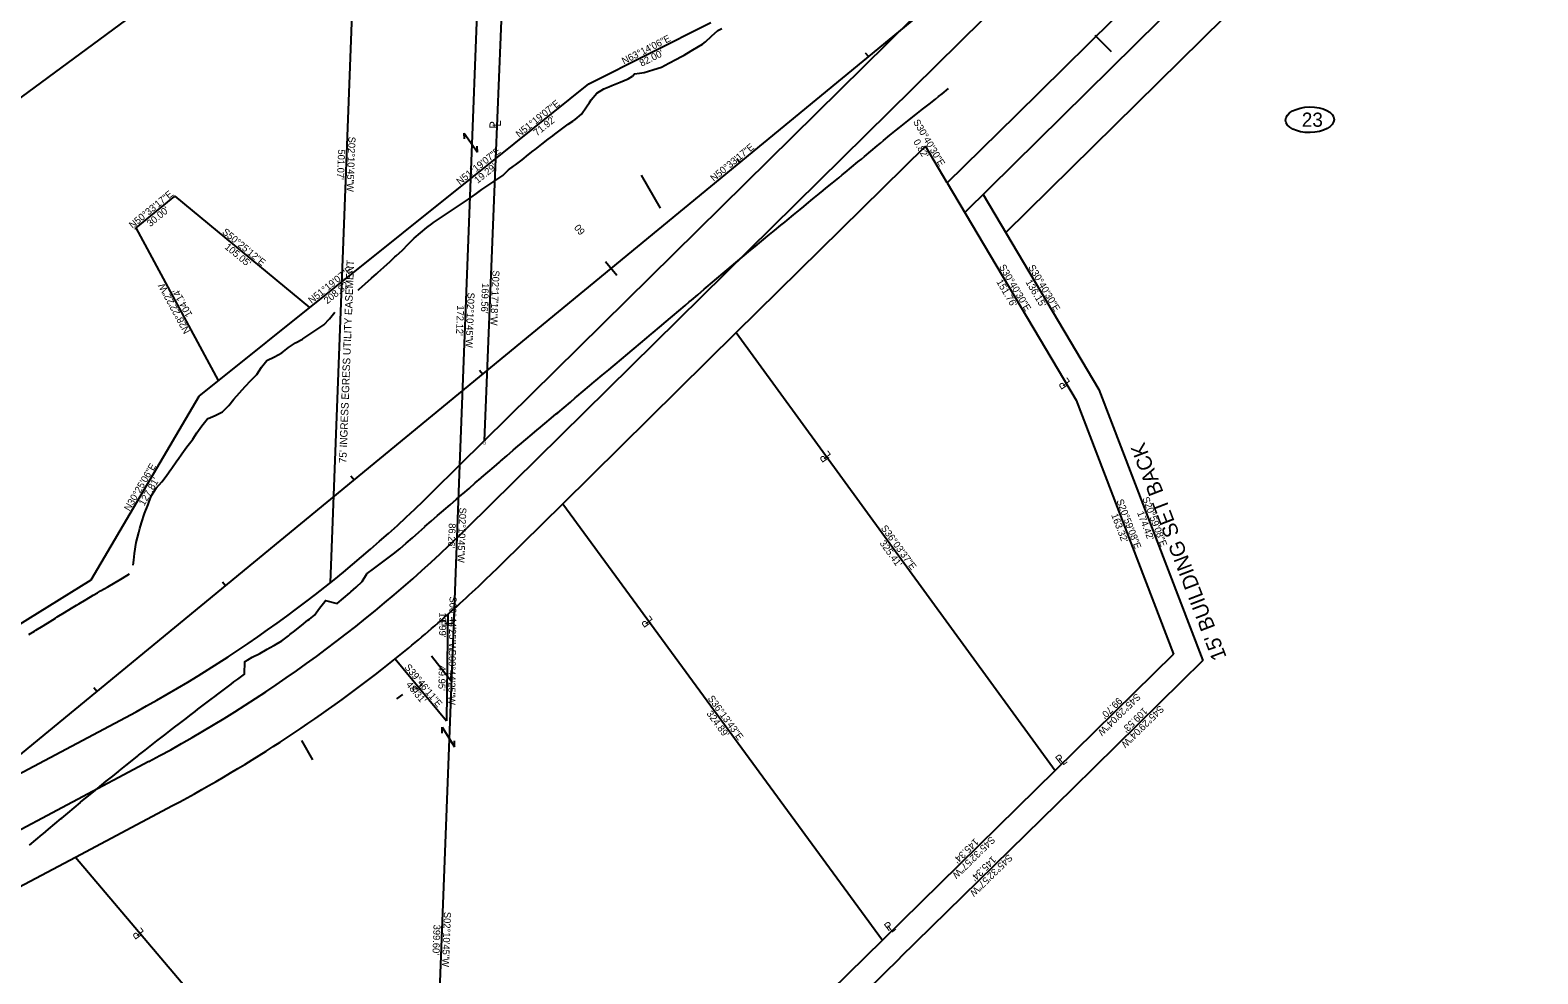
# Model space of a CAD drawing. Extents: x 1145508 to 2262867, y -3126236 to 2021677.
# Drawn here: x 1148734 to 1149640, y 2018227 to 2018793 of the extents above; entities that cross this region are included whole.
import ezdxf

# ---------------------------------------------------------------- set-up
doc = ezdxf.new("R2010")
doc.units = 0
for name, color, linetype in [('Default', 7, 'Continuous'), ('DSN_RDWY_Alignment Annotation', 7, 'Continuous'), ('DSN_RDWY_Const Limits', 7, 'Continuous'), ('DSN_ROW_Annotation', 7, 'Continuous'), ('DSN_ROW_Esmnt', 7, 'Continuous'), ('DSN_ROW_Line', 7, 'Continuous'), ('DSN_ROW_Line-Annotation', 7, 'Continuous'), ('DSN_ROW_Prop-Line', 7, 'Continuous'), ('DSN_ROW_Prop-Line-Annotation', 7, 'Continuous'), ('E_Const Align', 7, 'Continuous'), ('EX_PRIMARY_CTL', 7, 'Continuous'), ('EX_QSECTION', 7, 'Continuous'), ('EX_ROW', 7, 'Continuous'), ('EX_ROW_ANNOT', 7, 'Continuous'), ('EX_SIGN', 7, 'Continuous')]:
    doc.layers.add(name, color=color, linetype=linetype)

msp = doc.modelspace()

# ---------------------------------------------------------------- linework, layer by layer
at = {"layer": 'Default'}
for p, q in [((1149548.89, 2019038.9), (1148996.69, 2018494.41)), ((1148805.68, 2018354.22), (1148567.35, 2018227.75))]:
    msp.add_line(p, q, dxfattribs=at)
msp.add_arc((1148422, 2019077.24), 818.51, 297.95351, 314.5973, dxfattribs=at)
at = {"layer": 'DSN_RDWY_Alignment Annotation'}
for p, q in [((1149235.9, 2018779.81), (1149237.81, 2018777.49)), ((1149158.68, 2018716.28), (1149160.58, 2018713.96)), ((1149079.97, 2018654.55), (1149086.71, 2018646.35)), ((1149004.23, 2018589.21), (1149006.14, 2018586.89)), ((1148927.01, 2018525.67), (1148928.91, 2018523.36)), ((1148849.78, 2018462.14), (1148851.69, 2018459.82)), ((1148772.56, 2018398.61), (1148774.47, 2018396.29))]:
    msp.add_line(p, q, dxfattribs=at)
at = {"layer": 'DSN_RDWY_Const Limits'}
for points in [[(1148931.32, 2018637.33), (1148931.86, 2018637.82), (1148935.61, 2018641.14), (1148939.35, 2018644.45), (1148942.37, 2018647.15), (1148943.1, 2018647.77), (1148946.8, 2018651.14), (1148950.51, 2018654.5), (1148953.45, 2018657.17), (1148954.21, 2018657.87), (1148957.92, 2018661.24), (1148961.41, 2018664.86), (1148964.09, 2018667.7), (1148964.87, 2018668.53), (1148968.69, 2018671.76), (1148972.62, 2018674.85), (1148975.6, 2018677.18), (1148976.55, 2018677.93), (1148980.71, 2018680.75), (1148984.92, 2018683.51), (1148988.01, 2018685.56), (1148989.12, 2018686.28), (1148993.34, 2018689.01), (1148997.52, 2018691.81), (1149000.46, 2018693.91), (1149001.59, 2018694.72), (1149005.67, 2018697.63), (1149009.83, 2018700.44), (1149012.73, 2018702.47), (1149013.97, 2018703.28), (1149018.16, 2018706.06), (1149021.72, 2018709.61), (1149024.63, 2018711.69), (1149025.79, 2018712.52), (1149029.74, 2018715.6), (1149033.66, 2018718.7), (1149036.35, 2018720.83), (1149037.58, 2018721.81), (1149041.55, 2018724.85), (1149045.53, 2018727.88), (1149048.2, 2018729.92), (1149049.51, 2018730.92), (1149053.48, 2018733.96), (1149057.5, 2018736.94), (1149060.22, 2018738.81), (1149061.64, 2018739.78), (1149065.5, 2018742.96), (1149068.43, 2018747.27), (1149070.31, 2018750.03), (1149071.36, 2018751.57), (1149074.59, 2018755.52), (1149078.9, 2018758.15), (1149081.94, 2018759.38), (1149083.76, 2018760.12), (1149088.61, 2018762.09), (1149093.42, 2018764.12), (1149096.05, 2018765.8), (1149097.4, 2018767.14), (1149100.37, 2018767.53), (1149103.15, 2018768.02), (1149108.31, 2018769.62), (1149111.5, 2018770.49), (1149113.51, 2018771.17), (1149117.95, 2018773.65), (1149122.54, 2018775.94), (1149125.2, 2018777.27), (1149127.04, 2018778.34), (1149131.41, 2018780.89), (1149135.75, 2018783.5), (1149138.16, 2018785.01), (1149139.9, 2018786.31), (1149143.55, 2018789.75), (1149147.27, 2018793.1), (1149149.7, 2018794.43)], [(1148733.93, 2018303.9), (1148737.73, 2018307.16), (1148741.56, 2018310.37), (1148742.1, 2018310.83), (1148745.39, 2018313.58), (1148749.23, 2018316.79), (1148753.04, 2018320.02), (1148753.35, 2018320.29), (1148756.85, 2018323.27), (1148760.71, 2018326.45), (1148764.53, 2018329.66), (1148764.6, 2018329.72), (1148766.77, 2018331.54), (1148768.39, 2018332.85), (1148772.27, 2018336.01), (1148775.95, 2018339.01), (1148776.14, 2018339.17), (1148780.02, 2018342.32), (1148783.91, 2018345.46), (1148787.37, 2018348.24), (1148787.81, 2018348.59), (1148791.69, 2018351.74), (1148795.58, 2018354.89), (1148798.73, 2018357.44), (1148799.47, 2018358.03), (1148803.4, 2018361.12), (1148807.33, 2018364.21), (1148810.34, 2018366.55), (1148811.29, 2018367.27), (1148815.26, 2018370.32), (1148819.23, 2018373.36), (1148821.87, 2018375.4), (1148823.18, 2018376.42), (1148827.15, 2018379.47), (1148831.11, 2018382.52), (1148833.39, 2018384.28), (1148835.08, 2018385.58), (1148839.03, 2018388.64), (1148843.01, 2018391.67), (1148845.18, 2018393.26), (1148847.06, 2018394.63), (1148851.1, 2018397.58), (1148855.01, 2018400.7), (1148856.68, 2018402.05), (1148858.98, 2018403.74), (1148863.02, 2018406.71), (1148863.22, 2018414.33), (1148865.02, 2018415.35), (1148867.65, 2018416.82), (1148872.19, 2018419.16), (1148876.65, 2018421.61), (1148878.16, 2018422.46), (1148881.07, 2018424.12), (1148885.43, 2018426.69), (1148889.4, 2018429.73), (1148890.38, 2018430.48), (1148893.36, 2018432.78), (1148896.47, 2018435.3), (1148897.25, 2018435.93), (1148901.19, 2018439), (1148902.15, 2018439.73), (1148905.09, 2018442.14), (1148908.17, 2018446.27), (1148911.24, 2018450.4), (1148911.67, 2018450.99), (1148918.75, 2018449.14), (1148922.6, 2018452.34), (1148926.4, 2018455.59), (1148926.92, 2018456.04), (1148930.12, 2018458.93), (1148933.8, 2018462.33), (1148936.55, 2018466.86), (1148936.77, 2018467.03), (1148940.55, 2018469.87), (1148944.54, 2018472.88), (1148948.54, 2018475.89), (1148948.54, 2018475.89), (1148952.54, 2018478.9), (1148956.45, 2018482.02), (1148960.2, 2018485.27), (1148960.23, 2018485.29), (1148963.97, 2018488.61), (1148967.72, 2018491.93), (1148971.34, 2018495.14), (1148971.46, 2018495.25), (1148975.21, 2018498.56), (1148978.96, 2018501.88), (1148982.56, 2018505.04), (1148982.72, 2018505.18), (1148986.51, 2018508.44), (1148990.32, 2018511.68), (1148993.68, 2018514.54), (1148994.13, 2018514.92), (1148997.9, 2018518.2), (1149001.67, 2018521.49), (1149004.97, 2018524.31), (1149005.47, 2018524.74), (1149009.27, 2018527.99), (1149013.06, 2018531.25), (1149016.29, 2018534.05), (1149016.84, 2018534.53), (1149020.61, 2018537.82), (1149024.39, 2018541.1), (1149027.45, 2018543.75), (1149028.16, 2018544.38), (1149031.94, 2018547.66), (1149035.78, 2018550.86), (1149038.82, 2018553.4), (1149039.62, 2018554.06), (1149043.46, 2018557.26), (1149047.32, 2018560.45), (1149050.3, 2018562.92), (1149051.16, 2018563.64), (1149054.99, 2018566.86), (1149058.81, 2018570.08), (1149061.71, 2018572.52), (1149062.64, 2018573.31), (1149066.46, 2018576.53), (1149070.28, 2018579.76), (1149073.1, 2018582.14), (1149074.1, 2018582.98), (1149077.94, 2018586.18), (1149081.79, 2018589.38), (1149084.56, 2018591.69), (1149085.62, 2018592.58), (1149089.45, 2018595.8), (1149093.28, 2018599.01), (1149095.99, 2018601.27), (1149097.12, 2018602.22), (1149100.94, 2018605.45), (1149104.75, 2018608.68), (1149107.48, 2018610.99), (1149108.57, 2018611.91), (1149112.4, 2018615.13), (1149116.23, 2018618.35), (1149118.86, 2018620.55), (1149120.06, 2018621.56), (1149123.87, 2018624.79), (1149127.68, 2018628.04), (1149130.23, 2018630.22), (1149131.48, 2018631.28), (1149135.28, 2018634.53), (1149139.09, 2018637.78), (1149141.59, 2018639.91), (1149142.89, 2018641.02), (1149146.7, 2018644.26), (1149150.53, 2018647.48), (1149152.99, 2018649.54), (1149154.36, 2018650.7), (1149158.19, 2018653.91), (1149162.02, 2018657.12), (1149164.42, 2018659.13), (1149165.87, 2018660.32), (1149169.74, 2018663.48), (1149173.61, 2018666.65), (1149176.01, 2018668.61), (1149177.48, 2018669.82), (1149179.43, 2018671.44), (1149181.32, 2018673.01), (1149185.18, 2018676.19), (1149187.51, 2018678.11), (1149189.04, 2018679.37), (1149192.89, 2018682.56), (1149196.75, 2018685.73), (1149199, 2018687.58), (1149200.62, 2018688.91), (1149204.48, 2018692.08), (1149208.36, 2018695.24), (1149210.54, 2018697.03), (1149212.23, 2018698.41), (1149216.09, 2018701.58), (1149219.97, 2018704.73), (1149222.08, 2018706.45), (1149223.84, 2018707.9), (1149227.68, 2018711.1), (1149231.52, 2018714.3), (1149233.56, 2018715.99), (1149235.38, 2018717.49), (1149239.19, 2018720.72), (1149243.01, 2018723.94), (1149244.98, 2018725.59), (1149246.85, 2018727.15), (1149250.73, 2018730.3), (1149254.61, 2018733.46), (1149256.54, 2018735.03), (1149258.49, 2018736.61), (1149262.41, 2018739.72), (1149266.33, 2018742.82), (1149268.23, 2018744.31), (1149270.27, 2018745.91), (1149274.21, 2018748.98), (1149278.17, 2018752.04), (1149279.97, 2018753.49), (1149282.05, 2018755.2), (1149285.85, 2018758.44)], [(1148796.25, 2018472.11), (1148796.55, 2018475.14), (1148796.95, 2018479.14), (1148798.02, 2018485.71), (1148799.6, 2018491.65), (1148800.25, 2018494.08), (1148801.19, 2018497.59), (1148803.09, 2018503.16), (1148805.12, 2018508.56), (1148805.81, 2018510.4), (1148807.15, 2018513.96), (1148810.08, 2018518.26), (1148813.39, 2018522.11), (1148814.21, 2018523.07), (1148816.48, 2018526.23), (1148818.87, 2018529.62), (1148819.47, 2018530.46), (1148822.45, 2018534.71), (1148823.17, 2018535.72), (1148825.44, 2018538.95), (1148828.43, 2018543.18), (1148831.6, 2018547.2), (1148832, 2018547.82), (1148834.43, 2018551.63), (1148837.44, 2018555.84), (1148840.6, 2018559.87), (1148841.23, 2018560.19), (1148845.38, 2018561.93), (1148849.92, 2018564.28), (1148853.48, 2018567.83), (1148853.67, 2018568.02), (1148856.7, 2018571.78), (1148860.06, 2018575.57), (1148863.37, 2018579.41), (1148863.37, 2018579.41), (1148866.85, 2018583.05), (1148870.4, 2018586.6), (1148873.23, 2018590.99), (1148873.24, 2018591.02), (1148876.49, 2018594.95), (1148881.04, 2018597.29), (1148885.41, 2018599.59), (1148885.55, 2018599.67), (1148889.45, 2018602.8), (1148893.62, 2018605.6), (1148897.97, 2018607.87), (1148898.16, 2018607.96), (1148902.33, 2018610.75), (1148906.5, 2018613.56), (1148910.14, 2018616.08), (1148910.61, 2018616.44), (1148914.07, 2018620.1), (1148917.33, 2018624)], [(1148733.44, 2018430.41), (1148736.93, 2018432.55), (1148737.74, 2018433.05), (1148742.04, 2018435.7), (1148746.34, 2018438.35), (1148749.61, 2018440.36), (1148750.61, 2018441.02), (1148754.9, 2018443.68), (1148759.2, 2018446.32), (1148762.06, 2018448.09), (1148763.5, 2018448.97), (1148767.87, 2018451.53), (1148772.22, 2018454.1), (1148774.73, 2018455.58), (1148776.58, 2018456.67), (1148780.99, 2018459.19), (1148785.35, 2018461.76), (1148787.68, 2018463.15), (1148789.7, 2018464.34), (1148794.05, 2018466.92)]]:
    msp.add_lwpolyline(points, dxfattribs=at)
at = {"layer": 'DSN_ROW_Esmnt'}
for p, q in [((1148797.98, 2018674.63), (1148821.15, 2018693.69)), ((1148797.98, 2018674.63), (1148821.15, 2018693.69)), ((1148821.15, 2018693.69), (1148902.12, 2018626.75)), ((1148821.15, 2018693.69), (1148902.12, 2018626.75)), ((1148847.47, 2018583), (1148797.98, 2018674.63)), ((1148847.47, 2018583), (1148797.98, 2018674.63))]:
    msp.add_line(p, q, dxfattribs=at)
at = {"layer": 'DSN_ROW_Line'}
for p, q in [((1149069.97, 2018761.14), (1149143.19, 2018798.06)), ((1149013.83, 2018716.19), (1149069.97, 2018761.14)), ((1148998.77, 2018704.13), (1149013.83, 2018716.19)), ((1148835.76, 2018573.62), (1148998.77, 2018704.13)), ((1148771.05, 2018463.4), (1148835.76, 2018573.62)), ((1148642.51, 2018383.55), (1148771.05, 2018463.4))]:
    msp.add_line(p, q, dxfattribs=at)
at = {"layer": 'DSN_ROW_Line-Annotation'}
msp.add_ellipse((1149502.94, 2018739.58), major_axis=(14.54, 0.23), ratio=0.529773, dxfattribs=at)
at = {"layer": 'DSN_ROW_Prop-Line'}
for p, q in [((1148375.95, 2018492.82), (1149008.48, 2018959.29)), ((1148933.53, 2018962.14), (1148914.48, 2018461.44)), ((1149023.52, 2018958.62), (1149013.83, 2018716.19)), ((1149295.7, 2018683.91), (1149563.53, 2018948)), ((1149320.31, 2018671.82), (1149594.73, 2018942.42)), ((1149272.05, 2018723.79), (1149272.46, 2018723.08)), ((1149013.83, 2018716.19), (1149007.06, 2018546.76)), ((1149285.19, 2018701.63), (1149362.61, 2018571.11)), ((1149306.7, 2018694.76), (1149376.16, 2018577.67)), ((1149158.46, 2018611.78), (1149350, 2018348.72)), ((1149376.16, 2018577.67), (1149438.62, 2018414.82)), ((1149362.61, 2018571.11), (1149421.1, 2018418.62)), ((1149054.24, 2018509.02), (1149246.25, 2018246.94)), ((1148985.2, 2018442.59), (1148985.02, 2018428.6)), ((1148985.02, 2018428.6), (1148984.37, 2018378.65)), ((1148953.46, 2018415.79), (1148984.37, 2018378.65)), ((1149421.1, 2018418.62), (1149350, 2018348.72)), ((1149438.62, 2018414.82), (1149360.52, 2018338.03)), ((1149350, 2018348.72), (1149246.25, 2018246.94)), ((1149360.51, 2018338.02), (1149256.76, 2018236.23)), ((1148761.6, 2018296.87), (1149062.47, 2017941.97)), ((1149246.25, 2018246.94), (1149174.9, 2018177.17)), ((1149256.74, 2018236.22), (1149194.74, 2018175.59))]:
    msp.add_line(p, q, dxfattribs=at)
at = {"layer": 'DSN_ROW_Prop-Line-Annotation'}
for p, q in [((1148995.13, 2018728.05), (1148994.92, 2018731.59)), ((1148994.92, 2018731.59), (1149002.98, 2018720.18)), ((1149002.98, 2018720.18), (1149002.78, 2018723.72)), ((1148981.86, 2018371.31), (1148981.86, 2018374.86)), ((1148981.86, 2018374.86), (1148989.25, 2018363)), ((1148989.25, 2018363), (1148989.25, 2018366.55))]:
    msp.add_line(p, q, dxfattribs=at)
at = {"layer": 'E_Const Align'}
msp.add_line((1148677.53, 2018316.54), (1149639.88, 2019108.3), dxfattribs=at)
at = {"layer": 'EX_QSECTION'}
for p, q in [((1149008.48, 2018959.29), (1148998.77, 2018704.13)), ((1148998.77, 2018704.13), (1148992.23, 2018532.14)), ((1148992.23, 2018532.14), (1148988.95, 2018445.93)), ((1148988.95, 2018445.93), (1148973.75, 2018046.62))]:
    msp.add_line(p, q, dxfattribs=at)
at = {"layer": 'EX_ROW'}
for p, q in [((1149326.65, 2018742.52), (1149523.2, 2018936.33)), ((1149007.06, 2018546.76), (1149326.33, 2018861.58)), ((1149285.19, 2018701.63), (1149326.65, 2018742.52)), ((1149158.46, 2018611.78), (1149272.05, 2018723.79)), ((1149285.19, 2018701.63), (1149272.05, 2018723.79)), ((1149054.24, 2018509.02), (1149158.46, 2018611.78)), ((1148992.23, 2018532.14), (1149007.06, 2018546.76)), ((1148975.63, 2018515.77), (1148992.23, 2018532.14)), ((1149017.76, 2018473.05), (1149054.24, 2018509.02)), ((1148553.28, 2018254.25), (1148791.62, 2018380.72)), ((1148761.6, 2018296.87), (1148819.75, 2018327.73)), ((1148705.7, 2018267.2), (1148761.6, 2018296.87))]:
    msp.add_line(p, q, dxfattribs=at)
for radius, start, end in [(788.51, 297.95351, 314.5973), (848.51, 311.92551, 314.5973), (848.51, 308.78113, 311.58612), (848.51, 311.58612, 311.92551), (848.51, 297.95351, 308.78113)]:
    msp.add_arc((1148422, 2019077.24), radius, start, end, dxfattribs=at)
at = {"layer": 'EX_SIGN'}
for p, q in [((1149373.79, 2018790.45), (1149383.63, 2018780.52)), ((1149101.25, 2018706.24), (1149112.72, 2018686.56)), ((1148975.36, 2018417.76), (1148987.78, 2018401.78)), ((1148958.05, 2018394.47), (1148954.35, 2018391.79)), ((1148897.31, 2018366.83), (1148903.98, 2018355.25))]:
    msp.add_line(p, q, dxfattribs=at)

# ---------------------------------------------------------------- texts
at = {"layer": 'DSN_RDWY_Alignment Annotation'}
for s, rotation, p in [('N50°33\'17"E', 39.44534, (1149144.96, 2018702.27)), ('60', 129.44534, (1149067.94, 2018672.48))]:
    msp.add_text(s, height=4.2, rotation=rotation, dxfattribs=at).set_placement(p)
at = {"layer": 'DSN_ROW_Annotation'}
for s, rotation, p in [('N63°14\'06"E', 26.76495, (1149090.94, 2018772.72)), ("82.00'", 26.76495, (1149101.6, 2018771.38)), ('N51°19\'07"E', 38.68144, (1149028.02, 2018728.7)), ("71.92'", 38.68144, (1149038.72, 2018729.59)), ('S30°40\'30"E', 300.67507, (1149264.48, 2018738.31)), ('S02°10\'45"W', 267.82095, (1148925.58, 2018729.51)), ("501.07'", 267.82095, (1148919.29, 2018721.83)), ('N51°19\'07"E', 38.68144, (1148992.42, 2018700.2)), ("0.82'", 300.67507, (1149264.58, 2018726.38)), ("19.29'", 38.68144, (1149003.12, 2018701.08)), ('N50°33\'17"E', 39.44534, (1148795.82, 2018674.02)), ('N50°33\'17"E', 39.44534, (1148795.82, 2018674.02)), ("30.00'", 39.44534, (1148806.51, 2018675.04)), ("30.00'", 39.44534, (1148806.51, 2018675.04)), ('S50°25\'12"E', 320.42013, (1148849.29, 2018671.59)), ('S50°25\'12"E', 320.42013, (1148849.29, 2018671.59)), ("105.05'", 320.42013, (1148850.79, 2018662.57)), ("105.05'", 320.42013, (1148850.79, 2018662.57)), ('N51°19\'07"E', 38.68144, (1148903.39, 2018628.92)), ('S02°17\'18"W', 267.71174, (1149012.05, 2018649.2)), ('S30°40\'30"E', 300.67507, (1149316.12, 2018651.25)), ('S30°40\'30"E', 300.67507, (1149333.65, 2018651.09)), ('N28°22\'22"W', 118.37279, (1148830.52, 2018612.49)), ('N28°22\'22"W', 118.37279, (1148830.52, 2018612.49)), ("208.82'", 38.68144, (1148912.76, 2018628.74)), ("169.56'", 267.71174, (1149005.74, 2018641.53)), ("151.76'", 300.67507, (1149314.48, 2018642.25)), ("136.15'", 300.67507, (1149332.01, 2018642.09)), ("104.14'", 118.37279, (1148831.9, 2018622.56)), ("104.14'", 118.37279, (1148831.9, 2018622.56)), ('N30°25\'06"E', 59.58164, (1148793.99, 2018504.26)), ("127.81'", 59.58164, (1148802.81, 2018507.43)), ('S20°59\'08"E', 290.98559, (1149386.69, 2018510.84)), ('S20°59\'08"E', 290.98559, (1149402.23, 2018512.22)), ("163.32'", 290.98559, (1149383.56, 2018502.24)), ("174.42'", 290.98559, (1149399.1, 2018503.62)), ('S36°03\'37"E', 306.06023, (1149245.09, 2018494.33)), ("325.41'", 306.06023, (1149244.3, 2018485.22)), ('S00°44\'25"W', 269.25983, (1148986.24, 2018453.35)), ("13.99'", 269.25983, (1148980.11, 2018443.81)), ('S00°44\'25"W', 269.25983, (1148985.82, 2018421.38)), ('S39°46\'11"E', 309.76983, (1148958.88, 2018410.68)), ("49.95'", 269.25983, (1148979.7, 2018411.84)), ("48.31'", 309.76983, (1148959.78, 2018400.22)), ('S36°13\'43"E', 306.22872, (1149141.06, 2018392.03)), ('S45°29\'04"W', 224.51551, (1149398.85, 2018395.49)), ("324.89'", 306.22872, (1149140.31, 2018382.92)), ("99.70'", 224.51551, (1149387.79, 2018393.03)), ('S45°29\'04"W', 224.51551, (1149412.87, 2018388.24)), ("109.53'", 224.51551, (1149403.03, 2018386.97)), ('S45°32\'57"W', 224.45079, (1149311.44, 2018309.63)), ("145.34'", 224.45079, (1149301.59, 2018308.38)), ('S45°32\'57"W', 224.45079, (1149321.95, 2018298.93)), ("145.34'", 224.45079, (1149312.1, 2018297.67))]:
    msp.add_text(s, height=4.2, rotation=rotation, dxfattribs=at).set_placement(p)
at = {"layer": 'DSN_ROW_Esmnt'}
for p in [(1148820.15, 2018692.69), (1148796.98, 2018673.63)]:
    msp.add_text('b', height=2, dxfattribs=at).set_placement(p)
at = {"layer": 'DSN_ROW_Line-Annotation'}
msp.add_text('23', height=8.5, dxfattribs=at).set_placement((1149498.12, 2018735.37))
at = {"layer": 'DSN_ROW_Prop-Line'}
for s, height, rotation, p in [("75' INGRESS EGRESS UTILITY EASEMENT", 4.5, 87.82095, (1148924.26, 2018533.22)), ("15' BUILDING SET BACK", 9, 110.98559, (1149453.11, 2018416.94))]:
    msp.add_text(s, height=height, rotation=rotation, dxfattribs=at).set_placement(p)
at = {"layer": 'DSN_ROW_Prop-Line-Annotation'}
for s, rotation, p in [('P', 90, (1149015.21, 2018734.29)), ('L', 90, (1149017.12, 2018735.45)), ('L', 125.89343, (1149359.2, 2018582.08)), ('P', 125.89343, (1149358.33, 2018580.02)), ('L', 125.89343, (1149215.6, 2018538.22)), ('P', 125.89343, (1149214.73, 2018536.15)), ('P', 89.8423, (1148986.42, 2018435.15)), ('L', 89.8423, (1148988.34, 2018436.31)), ('L', 125.89343, (1149108.56, 2018439.12)), ('P', 125.89343, (1149107.69, 2018437.05)), ('P', 125.89343, (1148969.75, 2018397.66)), ('L', 125.89343, (1148970.62, 2018399.73)), ('P', 37.94139, (1149352.55, 2018352.46)), ('L', 37.94139, (1149354.65, 2018351.67)), ('P', 37.94139, (1149249.7, 2018251.98)), ('P', 125.89343, (1148802.06, 2018249.79)), ('L', 125.89343, (1148802.93, 2018251.86)), ('L', 37.94139, (1149251.8, 2018251.18))]:
    msp.add_text(s, height=5, rotation=rotation, dxfattribs=at).set_placement(p)
at = {"layer": 'EX_PRIMARY_CTL'}
msp.add_text('G', height=2.5, dxfattribs=at).set_placement((1149005.77, 2018544.63))
at = {"layer": 'EX_ROW_ANNOT'}
for s, p in [('S02°10\'45"W', (1148997.07, 2018635.86)), ('S02°10\'45"W', (1148997.07, 2018635.86)), ("172.12'", (1148990.78, 2018628.18)), ("172.12'", (1148990.78, 2018628.18)), ('S02°10\'45"W', (1148992.16, 2018506.76)), ('S02°10\'45"W', (1148992.16, 2018506.76)), ("86.26'", (1148985.8, 2018497.38)), ("86.26'", (1148985.8, 2018497.38)), ('S02°10\'45"W', (1148982.92, 2018264)), ('S02°10\'45"W', (1148982.92, 2018264)), ("399.60'", (1148976.63, 2018256.32)), ("399.60'", (1148976.63, 2018256.32))]:
    msp.add_text(s, height=4.2, rotation=267.82095, dxfattribs=at).set_placement(p)

doc.saveas('drawing.dxf')
